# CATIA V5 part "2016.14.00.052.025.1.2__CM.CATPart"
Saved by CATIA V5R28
Part number: 2016.14.00.052.025.1.2__CM
Property "id_number": "2016.14.00.052.025.1.2"
Publications: "Absolute Axis System", "driver", "slider", "base", "cam diagram"
Bounding box of the stored display mesh (mm): x -25 to 120, y -49 to 49, z 0 to 165
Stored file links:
  N:\B2\Normteile\K\2016\11-14\005\cm\2016.14.00.052.025.1.2__CM.CATPart
  H:\CAD_Startmodelle\Tests\fill-in_PRT-SL_TEMPLATE.xlsx
  H:\CAD_Startmodelle\V5-R24\R24_TEMPLATE_PRT_FIBRO_CAM_TECNOLOGIES_INDEX.xlsx
  H:\z_Einordnen\170511__Anfrage_TK_HN\170511__CC01_TKHN.CATPart
  N:\B2\Normteile\K\2016\9xxx\2016.9024.1705.001\Entwurf_\170511__CC01_TKHN.CATPart
  N:\B2\Normteile\K\2016\9xxx\2016.9024.1707.006\Konstruktion\2016.9024.1707.006__HP__CUSTOMIZED_CAM_CM.CATPart
  N:\B2\Normteile\K\2016\9xxx\2016.9024.1707.005\Konstruktion\2016.9024.1707.005__HP__CUSTOMIZED_CAM_CM.CATPart
  N:\B2\Normteile\K\2016\9xxx\2016.9024.1707.008\Konstruktion\2016.9024.1707.008__HP__CUSTOMIZED_CAM_CM.CATPart
  N:\B2\Normteile\K\2016\9xxx\2016.9024.1707.009\Konstruktion\2016.9024.1707.009__HP__CUSTOMIZED_CAM_CM.CATPart
  N:\B2\Normteile\K\2016\9xxx\2016.9024.1707.010\Konstruktion\2016.9024.1707.010__HP__CUSTOMIZED_CAM_CM.CATPart
  N:\B2\Normteile\K\2016\9xxx\2016.9024.1708.002\Konstruktion\2016.9024.1708.002__HP__CUSTOMIZED_CAM_CM.CATPart
  N:\B2\Normteile\K\2016\9xxx\2016.9024.1802.001\Konstruktion\2016.9024.1802.001__HP__CUSTOMIZED_CAM_CM.CATPart
  N:\B2\Normteile\K\2016\9xxx\2016.9024.1802.002\Konstruktion\2016.9024.1802.002__HP__CUSTOMIZED_CAM_CM.CATPart
  N:\B2\Normteile\K\2016\9xxx\2016.9024.1811.003\Konstruktion\2016.9024.1811.003__HP__CUSTOMIZED_CAM_CM.CATPart
  N:\B2\Normteile\K\2016\9xxx\2016.9015.1811.001\Konstruktion\am\2016.9015.1811.001__AM__FCC_HV_DMC_0125-00.CATPart
  N:\B2\Normteile\K\2016\9xxx\2016.9024.1811.009\Konstruktion\2016.9024.1811.009__HP__CUSTOMIZED_CAM_CM.CATPart
  N:\B2\Normteile\K\2016\9xxx\2016.9024.1911.002\Konstruktion\am\2016.9024.1911.002__AM__CUSTOMIZED_CAM_CM.CATPart
  N:\B2\Normteile\K\2016\9xxx\2016.9024.2002.006\Konstruktion\2016.9024.2002.006__AM.CATPart
  N:\B2\Normteile\K\2016\9xxx\2016.9024.2004.001\Konstruktion\2016.9024.2004.001__AM__FCC_HV_CAEC_0260-45.CATPart
  N:\B2\Normteile\K\2016\9xxx\2016.9024.2006.002\Konstruktion\2016.9024.2006.002__AM__FCC_HV_CAEC_0260-40.CATPart
  N:\B2\Normteile\K\2016\9xxx\2016.9024.2006.005\Konstruktion\am\2016.9024.2006.005__AM__CFCC_HV_AEPC_0080-65.CATPart
  N:\B2\Normteile\K\2016\9xxx\2016.9024.2006.004\Konstruktion\am\2016.9024.2006.004__AM__CFCC_HV_AEC_0210-35.CATPart
  N:\B2\Normteile\K\2016\9xxx\2016.9026.2006.001\Konstruktion\am\2016.9026.2006.001__AM__FCC_LV_CAEC_0180-40.CATPart
  N:\B2\Normteile\K\2016\9xxx\2016.9015.2007.001\Konstruktion\am\2016.9015.2007.001__AM__FCC_HV_CDMPC_0090-00.CATPart
  N:\B2\Normteile\K\2016\9xxx\2016.9024.2005.001\Konstruktion\am\2016.9024.2005.001__AM__CFCC_HV_AEPC_1400-70.CATPart
  N:\B2\Normteile\K\2016\9xxx\2016.9024.2007.004\Konstruktion\am\2016.9024.2007.004__AM__CFCC_HV_AEC_1250-80.CATPart
  N:\B2\Normteile\K\2016\11-14\005\2016.11.00.052.040.1.02__AS__DIE_MOUNT_CAM__W52_A0_S40.CATProduct
  N:\B2\Normteile\K\2016\11-14\005\cm\2016.11.00.052.025.1.2__CM.CATPart
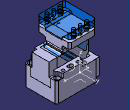
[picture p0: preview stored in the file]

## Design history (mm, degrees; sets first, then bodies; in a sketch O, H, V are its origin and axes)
Parameters
  group "process_parameters"
    modeltype = ""
    stocklist = ""
    id_number = "2016.14.00.052.025.1.2"
    id_number_rough_part = ""
    revision_index = ""
    revision_date = ""
    revision_description = ""
    category = ""
    material = ""
    manufacturing_information = ""
    standard = ""
  group "release_parameters_startmodel"
    sm_revision_index = "2016_00" {design table}
    sm_revision_date = "20.08.2016" {design table}
    sm_revision_name = "Meyer" {design table}
    sm_revision_description = "new part template FIBRO cam tecnologies" {design table}
AxisSystem1: origin (0, 0, 0), X (1, 0, 0), Y (0, 1, 0), Z (0, 0, 1)
Set1 "reference elements"
  Sketch1 "cam diagram" on ZX plane of AxisSystem1, origin (0, 0, 0), H (-1, 0, 0), V (0, 0, 1)
    line L1 (0, 0) -> (25, 0)
    line L2 (25, 0) -> (0, 25)
    point P2 (0, 25)
    line L3 (0, 25) -> (0, 0)
    length L1 = 25
    angle H L2 = 45
    horizontal: L1 H
    coincidence: P2 V
    vertical: L3 V
Body1 "finished_part" (main body)
  Body2 "rough_part"
  Add1 "rough_part": tool Body2
  Body3 "milling operations"
  Remove1 "milling operations": tool Body3
  Body4 "drilling operations"
  Remove2 "drilling operations": tool Body4
Body5 "driver"
  Solid1: solid without history
Body6 "slider"
  Solid2: solid without history
Body7 "base"
  Solid3: solid without history
Body8 "opened position"
  Body9 "slider"
    Body10 "slider"
      Solid4: linked copy from another document
    Assemble1: tool Body10
    Translate1: FirstPoint vertex [element of Sketch1 | element of Sketch1], SecondPoint vertex [element of Sketch1 | element of Sketch1], ToTransfor Assemble1
  Assemble2: tool Body9
  Body11 "driver"
    Body12 "driver"
      Solid5: linked copy from another document
    Assemble3: tool Body12
    Translate2: FirstPoint vertex [element of Sketch1 | element of Sketch1], SecondPoint vertex [element of Sketch1 | element of Sketch1], ToTransfor Assemble3
  Assemble4: tool Body11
